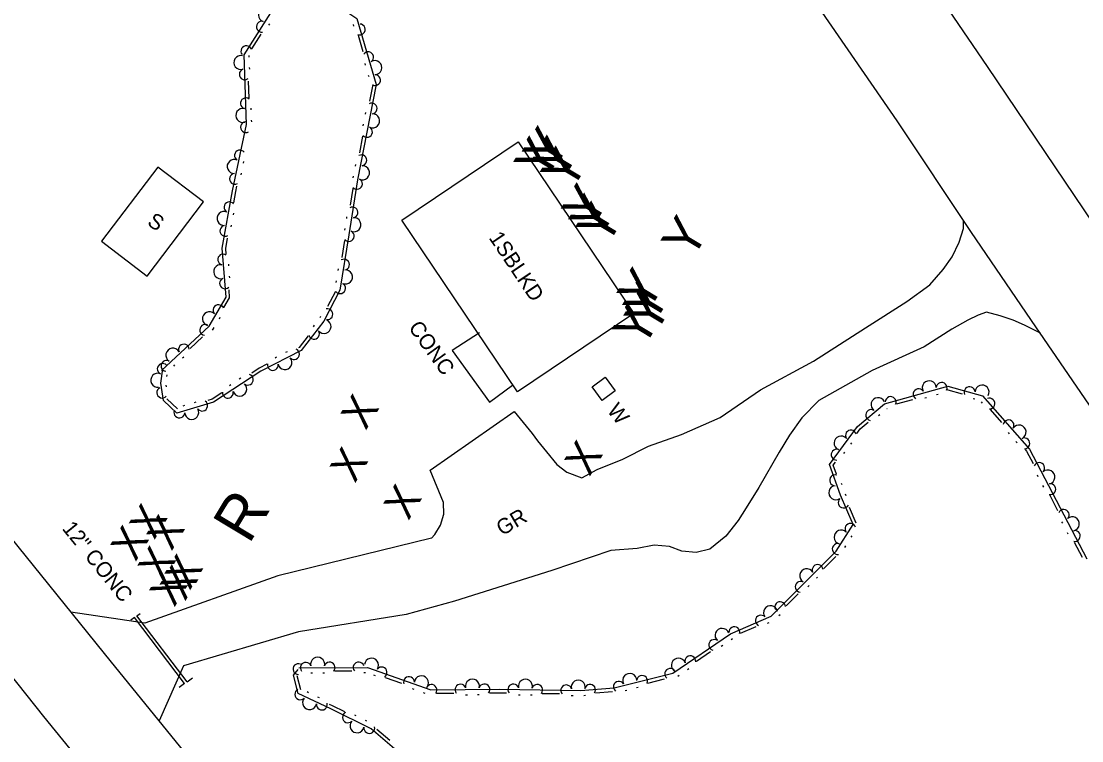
# Model space of a CAD drawing. Extents: x 2030130 to 2036320, y 723205 to 762423.
# Drawn here: x 2033931.4 to 2034186.4, y 759960.9 to 760133.9 of the extents above; entities that cross this region are included whole.
import ezdxf

# ---------------------------------------------------------------- set-up
doc = ezdxf.new("R2010")
doc.units = 0
for name, color, linetype in [('Draft_Station Cardinal Points', 7, 'Continuous'), ('Draft_Station Labels Major', 7, 'Continuous'), ('Draft_Station Tics Major', 7, 'Continuous'), ('Draft_Station Tics Minor', 7, 'Continuous'), ('Exist Terrain Model Ground Surface', 7, 'Continuous'), ('Old_Level_23', 7, 'Continuous'), ('Old_Level_26', 7, 'Continuous'), ('Old_Level_28', 7, 'Continuous')]:
    doc.layers.add(name, color=color, linetype=linetype)

msp = doc.modelspace()

# ---------------------------------------------------------------- linework, layer by layer
at = {"layer": 'Draft_Station Labels Major'}
for points in [[(2033718.38, 760730.67), (2033746.51, 760689.6), (2033774.62, 760648.49), (2033802.7, 760607.26), (2033830.67, 760566.06), (2033858.89, 760525.01), (2033886.8, 760483.79), (2033914.88, 760442.66), (2033945.45, 760397.69), (2033973.64, 760356.6), (2034001.68, 760315.42), (2034029.6, 760274.28), (2034057.68, 760233.24), (2034085.75, 760192.04), (2034113.77, 760150.87), (2034141.95, 760109.94), (2034159.83, 760083.11), (2034175.33, 760060.45), (2034197.95, 760027.35), (2034226.1, 759986.31), (2034253.95, 759945.01), (2034282.77, 759903.21), (2034311.52, 759860.74)], [(2034332.4, 759875.51), (2034304.28, 759916.6), (2034275.65, 759958.8), (2034247.14, 760000.6), (2034219.84, 760040.78), (2034191.61, 760081.68), (2034163.74, 760123.03), (2034135.88, 760163.98), (2034107.11, 760206.11), (2034080.34, 760245.23), (2034051.49, 760287.62), (2034022.91, 760329.48), (2033995.09, 760369.99), (2033966.89, 760411.11), (2033935.74, 760457.29), (2033907.97, 760498.26), (2033880.46, 760539.38), (2033851.33, 760582.23)], [(2034030.05, 760009.58), (2034030.88, 760010.51), (2034032.24, 760012.76), (2034033.03, 760015.36), (2034033.01, 760018.15), (2034029.8, 760025.93), (2034049.99, 760040.05), (2034054.29, 760034.81), (2034055.58, 760033.05), (2034057.7, 760030.34), (2034060.25, 760027.35), (2034062.66, 760025.49), (2034066.26, 760024.13), (2034069.95, 760026.16), (2034076.05, 760028.57), (2034082.29, 760031.75), (2034090.19, 760034.56), (2034099.49, 760038.61), (2034109.22, 760045.29), (2034121.91, 760052.16), (2034134.4, 760060.18), (2034144.39, 760066.5), (2034149.91, 760070.54), (2034153.14, 760074.19), (2034155.24, 760077.28), (2034156.93, 760080.74), (2034157.97, 760084.04), (2034157.98, 760085.88)], [(2033870.01, 760081.82), (2033911.82, 760030.81), (2033953.09, 759979.8), (2033994.45, 759928.93), (2034036.28, 759878.71)], [(2033854.41, 760068.47), (2033895.91, 760018.08), (2033936.8, 759966.77), (2033978.27, 759915.85)], [(2034176.39, 760058.91), (2034176.02, 760059.11), (2034172.66, 760060.81), (2034169.92, 760062.02), (2034166.79, 760063.03), (2034163.49, 760063.96), (2034161.5, 760063.2), (2034159.07, 760062.04), (2034155.21, 760059.9), (2034148.51, 760055.6), (2034136.01, 760049.94), (2034123.25, 760042.73), (2034119.1, 760038.56), (2034116.12, 760034.4), (2034113.68, 760030.26), (2034108.76, 760021.76), (2034105.78, 760016.92), (2034103.81, 760013.83), (2034100.88, 760010.08), (2034096.97, 760006.99), (2034093.71, 760006.13), (2034090.29, 760006.5), (2034087.27, 760007.63), (2034083.64, 760007.95), (2034079.57, 760007.11), (2034073.22, 760006.68), (2034059.04, 760001.81), (2034035.62, 759994.43), (2034023.96, 759991.23)], [(2034030.05, 760009.58), (2033993.17, 760000.52), (2033961.18, 759989.15), (2033943.35, 759991.84)], [(2034023.96, 759991.23), (2033998.09, 759987.07), (2033970.46, 759978.93), (2033964.58, 759965.66)]]:
    msp.add_lwpolyline(points, dxfattribs=at)
at = {"layer": 'Draft_Station Tics Major'}
for points in [[(2033965.17, 760049.92), (2033976.64, 760060.6), (2033980.72, 760067.59), (2033979.8, 760079.3), (2033982.22, 760093.09), (2033985.65, 760109.07), (2033985.02, 760125.83), (2033993.57, 760139.26), (2034003.02, 760140.7), (2034012.1, 760134.52), (2034016.82, 760118.72), (2034012.32, 760095.77), (2034010.24, 760082.56), (2034008.06, 760069.27), (2034004.22, 760061.81), (2033998.79, 760054.77), (2033989.08, 760049.77), (2033977.71, 760042.31), (2033968.89, 760039.65), (2033965.66, 760042.72), (2033965.01, 760046.89), (2033965.47, 760050.32)], [(2033991.01, 760132.95), (2033991.24, 760133.3)], [(2034011.22, 760133.14), (2034011.34, 760132.75)], [(2033986.92, 760127.29), (2033989.13, 760130.75)], [(2034012.44, 760130.51), (2034013.62, 760126.58)], [(2033986.27, 760125.27), (2033986.25, 760125.68)], [(2033986.38, 760122.4), (2033986.36, 760122.81)], [(2034014.05, 760123.71), (2034014.17, 760123.32)], [(2033986.23, 760115.42), (2033986.08, 760119.51)], [(2034014.87, 760120.96), (2034014.99, 760120.57)], [(2034015.99, 760118.72), (2034015.2, 760114.69)], [(2033986.75, 760112.56), (2033986.73, 760112.97)], [(2034014.24, 760111.96), (2034014.16, 760111.55)], [(2033986.86, 760109.69), (2033986.84, 760110.1)], [(2034013.69, 760109.14), (2034013.61, 760108.73)], [(2034013.54, 760106.24), (2034012.75, 760102.22)], [(2033984.91, 760099.75), (2033985, 760100.16)], [(2034011.8, 760099.48), (2034011.72, 760099.08)], [(2033984.31, 760096.95), (2033984.39, 760097.35)], [(2034011.25, 760096.66), (2034011.17, 760096.26)], [(2033982.55, 760090.23), (2033983.03, 760092.94), (2033983.3, 760094.22)], [(2034011.17, 760093.72), (2034010.53, 760089.67)], [(2033982.46, 760087.33), (2033982.53, 760087.73)], [(2034009.68, 760086.9), (2034009.62, 760086.49)], [(2033981.96, 760084.5), (2033982.03, 760084.9)], [(2034009.24, 760084.06), (2034009.17, 760083.66)], [(2033980.73, 760077.89), (2033980.62, 760079.26), (2033981.06, 760081.74)], [(2034009.18, 760081.17), (2034008.52, 760077.12)], [(2033981.36, 760075.06), (2033981.33, 760075.47)], [(2034007.65, 760074.36), (2034007.58, 760073.95)], [(2033981.59, 760072.2), (2033981.56, 760072.61)], [(2034007.18, 760071.52), (2034007.11, 760071.12)], [(2033980.2, 760065.07), (2033981.56, 760067.4), (2033981.41, 760069.31)], [(2034006.97, 760068.95), (2034005.09, 760065.3)], [(2033979.1, 760062.38), (2033979.31, 760062.74)], [(2034003.41, 760062.93), (2034003.22, 760062.57)], [(2033977.41, 760059.64), (2033977.61, 760059.83), (2033977.86, 760060.26)], [(2034001.87, 760060.79), (2034001.62, 760060.46)], [(2033972.03, 760055.19), (2033975.03, 760057.98)], [(2034000.45, 760058.26), (2033998.25, 760055.42), (2033998.13, 760055.35)], [(2033970.21, 760052.93), (2033970.51, 760053.21)], [(2033992.83, 760053.09), (2033992.47, 760052.9)], [(2033995.39, 760054.4), (2033995.02, 760054.22)], [(2033968.11, 760050.97), (2033968.41, 760051.25)], [(2033990.47, 760051.41), (2033988.66, 760050.48), (2033986.86, 760049.3)], [(2033966.47, 760048.5), (2033966.52, 760048.91)], [(2033984.23, 760048.06), (2033983.89, 760047.84)], [(2033966.39, 760046.01), (2033966.33, 760046.42)], [(2033981.83, 760046.49), (2033981.49, 760046.26)], [(2033998.21, 759978.45), (2034014.71, 759978.54), (2034029.92, 759973.13), (2034046.46, 759973.28), (2034065.88, 759972.97), (2034074, 759973.62), (2034088.09, 759977.12), (2034101.94, 759986.6), (2034111.75, 759990.86), (2034127.41, 760006.45), (2034131.46, 760012.9), (2034128.4, 760019.93), (2034125.74, 760027.32), (2034132.54, 760036.47), (2034138.98, 760041.92), (2034154.19, 760046.15), (2034162.58, 760043.86), (2034173.85, 760031), (2034187.64, 760004.61)], [(2034154.14, 760045.28), (2034154.19, 760045.3), (2034157.66, 760044.35)], [(2033969, 760040.68), (2033966.42, 760043.12)], [(2033973.43, 760042.3), (2033973.04, 760042.18)], [(2033979.66, 760044.57), (2033977.36, 760043.06), (2033976.3, 760042.74)], [(2034141.89, 760041.88), (2034145.84, 760042.98)], [(2034148.72, 760043.35), (2034149.11, 760043.46)], [(2034151.49, 760044.12), (2034151.88, 760044.23)], [(2034160.32, 760043.2), (2034160.72, 760043.09)], [(2034162.23, 760042.4), (2034162.5, 760042.09)], [(2033970.68, 760041.47), (2033970.29, 760041.35)], [(2034139.57, 760040.81), (2034139.63, 760040.82)], [(2034164.43, 760040.51), (2034167.13, 760037.42)], [(2034132.32, 760034.79), (2034133.14, 760035.9), (2034135.07, 760037.53)], [(2034137.53, 760039.08), (2034137.84, 760039.34)], [(2034168.71, 760034.99), (2034168.98, 760034.68)], [(2034130.93, 760032.24), (2034131.18, 760032.57)], [(2034170.6, 760032.83), (2034170.88, 760032.52)], [(2034129.22, 760029.94), (2034129.47, 760030.27)], [(2034172.8, 760030.94), (2034173.16, 760030.53), (2034174.72, 760027.56)], [(2034127.46, 760024.96), (2034126.66, 760027.18), (2034127.18, 760027.88)], [(2034175.69, 760024.82), (2034175.88, 760024.46)], [(2034128.82, 760022.4), (2034128.68, 760022.79)], [(2034177.02, 760022.28), (2034177.21, 760021.91)], [(2034129.8, 760019.79), (2034129.64, 760020.17)], [(2034178.71, 760019.92), (2034180.61, 760016.29)], [(2034132.2, 760013.23), (2034130.57, 760016.99)], [(2034181.57, 760013.55), (2034181.77, 760013.19)], [(2034130.98, 760009.82), (2034131.2, 760010.17)], [(2034182.9, 760011.01), (2034183.09, 760010.65)], [(2034129.45, 760007.39), (2034129.67, 760007.73)], [(2034184.6, 760008.66), (2034186.5, 760005.02)], [(2034124.38, 760002.28), (2034127.29, 760005.17)], [(2034122.63, 759999.96), (2034122.92, 760000.25)], [(2034120.6, 759997.94), (2034120.89, 759998.22)], [(2034115.37, 759993.31), (2034118.28, 759996.2)], [(2034113.62, 759990.99), (2034113.92, 759991.28)], [(2034110.91, 759989.16), (2034111.29, 759989.32)], [(2034104.35, 759986.75), (2034108.11, 759988.39)], [(2034099.77, 759983.62), (2034100.11, 759983.85)], [(2034102.14, 759985.24), (2034102.48, 759985.47)], [(2034093.79, 759980.03), (2034097.17, 759982.34)], [(2034025.69, 759955.1), (2034015.57, 759963.76), (2034005.92, 759968.55), (2033998.03, 759972.3), (2033996.91, 759976.7), (2033998.02, 759978.04)], [(2033998.66, 759973.14), (2033997.81, 759976.5)], [(2034001.09, 759977.24), (2034001.5, 759977.24)], [(2034003.96, 759977.25), (2034004.37, 759977.26)], [(2034006.83, 759977.68), (2034010.93, 759977.7)], [(2034013.81, 759977.3), (2034014.22, 759977.31)], [(2034016.14, 759976.72), (2034016.53, 759976.58)], [(2034018.99, 759976.15), (2034022.85, 759974.77)], [(2034089.28, 759976.45), (2034089.62, 759976.68)], [(2034091.65, 759978.07), (2034091.99, 759978.3)], [(2034025.42, 759973.43), (2034025.81, 759973.29)], [(2034079.41, 759973.7), (2034079.81, 759973.8)], [(2034082.1, 759974.79), (2034086.08, 759975.78)], [(2034000.55, 759972.46), (2034000.18, 759972.64)], [(2034003.14, 759971.23), (2034002.77, 759971.41)], [(2034028.12, 759972.47), (2034028.51, 759972.33)], [(2034031.33, 759972.33), (2034035.43, 759972.36)], [(2034038.3, 759971.98), (2034038.71, 759971.98)], [(2034041.17, 759972), (2034041.58, 759972.01)], [(2034044.04, 759972.44), (2034046.46, 759972.46), (2034048.12, 759972.43)], [(2034050.99, 759971.98), (2034051.4, 759971.97)], [(2034053.86, 759971.93), (2034054.27, 759971.93)], [(2034056.73, 759972.3), (2034060.83, 759972.23)], [(2034063.7, 759971.78), (2034064.11, 759971.77)], [(2034066.68, 759971.8), (2034067.09, 759971.83)], [(2034069.51, 759972.44), (2034073.6, 759972.77)], [(2034076.63, 759973.01), (2034077.03, 759973.1)], [(2034009.25, 759967.82), (2034006.28, 759969.29), (2034005.56, 759969.63)], [(2034012.01, 759966.91), (2034011.64, 759967.09)], [(2034014.58, 759965.63), (2034014.21, 759965.81)], [(2034020.09, 759960.97), (2034016.98, 759963.64)]]:
    msp.add_lwpolyline(points, dxfattribs=at)
for centre, radius, start, end in [((2033990.17, 760135.44), 1.69, 43.4477, 251.5202), ((2033989.32, 760132.58), 1.3, 75.9189, 276.7155), ((2034012.87, 760131.92), 1.3, 247.4322, 88.2288), ((2033985.57, 760126.7), 1.3, 18.2525, 219.049), ((2034014.87, 760125.24), 1.3, 305.0987, 145.8953), ((2033984.27, 760123.96), 1.69, 78.1239, 286.1964), ((2034016.48, 760122.73), 1.69, 272.6275, 120.7), ((2033985.19, 760121.12), 1.3, 110.5951, 311.3917), ((2034016.52, 760119.74), 1.3, 247.4322, 88.2288), ((2033985.46, 760114.15), 1.3, 52.9287, 253.7252), ((2034015.69, 760112.93), 1.3, 277.3405, 118.1371), ((2033984.75, 760111.25), 1.69, 78.1239, 286.1964), ((2034015.94, 760109.95), 1.69, 244.8693, 92.9418), ((2033985.51, 760108.43), 1.3, 96.3295, 297.1261), ((2034014.58, 760107.29), 1.3, 219.6741, 60.4706), ((2033984.05, 760101.61), 1.3, 38.6631, 239.4596), ((2034013.24, 760100.45), 1.3, 277.3405, 118.1371), ((2033982.65, 760098.98), 1.69, 63.8584, 271.9308), ((2034013.49, 760097.47), 1.69, 244.8693, 92.9418), ((2033982.85, 760096), 1.3, 96.3295, 297.1261), ((2034012.17, 760094.81), 1.3, 221.824, 62.6206), ((2033980.22, 760086.47), 1.69, 65.9807, 274.0531), ((2033981.53, 760089.16), 1.3, 40.7854, 241.582), ((2034011.09, 760087.92), 1.3, 279.4905, 120.287), ((2034011.45, 760084.96), 1.69, 247.0193, 95.0918), ((2033980.53, 760083.5), 1.3, 98.4519, 299.2484), ((2034010.19, 760082.25), 1.3, 221.4163, 62.2128), ((2033980.01, 760076.6), 1.3, 55.2973, 256.0938), ((2033979.42, 760073.68), 1.69, 80.4925, 288.565), ((2034009.06, 760075.37), 1.3, 279.0827, 119.8793), ((2034009.4, 760072.41), 1.69, 246.6115, 94.684), ((2033980.46, 760070.88), 1.3, 112.9637, 313.7603), ((2034008.13, 760069.71), 1.3, 221.4163, 62.2128), ((2033978.87, 760064.42), 1.3, 20.4481, 221.2447), ((2033976.71, 760062.36), 1.69, 45.6434, 253.7159), ((2034005.07, 760063.47), 1.3, 261.1881, 101.9846), ((2033975.67, 760059.7), 1.3, 61.4206, 262.2171), ((2034004.25, 760060.51), 1.69, 218.3484, 66.4209), ((2034001.85, 760058.74), 1.3, 193.1532, 33.9497), ((2033967.91, 760053.59), 1.69, 28.9494, 237.0219), ((2033970.57, 760054.95), 1.3, 3.7541, 204.5507), ((2033997.04, 760053.87), 1.3, 225.6657, 66.4623), ((2033994.86, 760051.83), 1.69, 193.1945, 41.267), ((2033965.47, 760050.29), 1.3, 43.1676, 243.9641), ((2033966.37, 760051.03), 1.3, 61.4206, 262.2171), ((2033991.94, 760051.25), 1.3, 167.9992, 8.7958), ((2033964.27, 760047.56), 1.69, 68.3628, 276.4353), ((2033985.94, 760047.71), 1.3, 231.7377, 72.5343), ((2034149.75, 760045.77), 1.69, 1.5027, 209.5752), ((2033965.36, 760044.61), 1.3, 117.2286, 318.0251), ((2033981.14, 760044.56), 1.3, 174.0713, 14.8678), ((2033983.99, 760045.45), 1.69, 199.2665, 47.339), ((2034147.2, 760044.21), 1.3, 33.9739, 234.7705), ((2034152.74, 760045.74), 1.3, 336.3074, 177.104), ((2034159.46, 760044.71), 1.3, 3.158, 203.9546), ((2034162.45, 760044.74), 1.69, 330.6868, 178.7593), ((2033974.96, 760041.48), 1.3, 215.2226, 56.0192), ((2034137.45, 760041.7), 1.69, 26.2178, 234.2903), ((2034140.49, 760042.34), 1.3, 336.3074, 177.104), ((2034164.23, 760041.97), 1.3, 271.9883, 112.7849), ((2033969.47, 760039.82), 1.3, 157.5562, 358.3527), ((2033972.45, 760039.86), 1.69, 182.7514, 30.8239), ((2034135.79, 760039.22), 1.3, 58.689, 259.4855), ((2034168.83, 760036.73), 1.3, 329.6548, 170.4513), ((2034130.92, 760034.29), 1.3, 14.1617, 214.9583), ((2034171.34, 760035.11), 1.69, 297.1836, 145.2561), ((2034128.55, 760032.48), 1.69, 39.357, 247.4295), ((2034172.61, 760032.41), 1.3, 271.9883, 112.7849), ((2034127.5, 760029.68), 1.3, 71.8282, 272.6247), ((2034176.21, 760026.48), 1.3, 316.0284, 156.825), ((2034127.11, 760023.53), 1.3, 70.5507, 271.3473), ((2034178.26, 760024.32), 1.69, 283.5572, 131.6297), ((2034127.31, 760020.55), 1.69, 95.746, 303.8185), ((2034178.87, 760021.39), 1.3, 258.3619, 99.1585), ((2034129.16, 760018.17), 1.3, 131.9088, 332.7054), ((2034182.1, 760015.22), 1.3, 316.0284, 156.825), ((2034184.15, 760013.05), 1.69, 283.5572, 131.6297), ((2034130.81, 760011.86), 1.3, 18.6426, 219.4392), ((2034128.59, 760009.87), 1.69, 43.8379, 251.9104), ((2034184.75, 760010.13), 1.3, 258.3619, 99.1585), ((2034127.75, 760007), 1.3, 76.3091, 277.1057), ((2034120.31, 760000.55), 1.69, 30.8359, 238.9084), ((2034122.93, 760001.99), 1.3, 5.6406, 206.4372), ((2034118.86, 759997.94), 1.3, 63.3071, 264.1037), ((2034113.92, 759993.02), 1.3, 5.6406, 206.4372), ((2034111.6, 759991.69), 1.69, 9.4693, 217.5418), ((2034109.29, 759989.79), 1.3, 41.9405, 242.7371), ((2034099.97, 759986.24), 1.69, 20.3208, 228.3932), ((2034102.9, 759987.01), 1.3, 344.2741, 185.0706), ((2034098.06, 759983.94), 1.3, 52.792, 253.5885), ((2034002.72, 759979.3), 1.69, 346.2544, 194.3269), ((2034092.31, 759980.01), 1.3, 355.1255, 195.9221), ((2033998.1, 759978.14), 1.3, 68.9478, 269.7443), ((2033999.85, 759978.46), 1.3, 18.7256, 219.5222), ((2034005.6, 759978.49), 1.3, 321.0591, 161.8557), ((2034012.57, 759978.53), 1.3, 18.7256, 219.5222), ((2034015.67, 759979.07), 1.69, 326.4115, 174.484), ((2034018.1, 759977.33), 1.3, 301.2163, 142.0128), ((2034089.47, 759979.07), 1.69, 20.3208, 228.3932), ((2034024.67, 759975), 1.3, 358.8827, 199.6793), ((2034027.65, 759974.81), 1.69, 326.4115, 174.484), ((2034077.73, 759975.39), 1.69, 359.9317, 208.0042), ((2034080.71, 759975.29), 1.3, 334.7364, 175.533), ((2034087.48, 759976.97), 1.3, 32.4029, 233.1995), ((2034030.09, 759973.13), 1.3, 321.2742, 162.0707), ((2034037.06, 759973.2), 1.3, 18.9406, 219.7372), ((2034039.93, 759974.04), 1.69, 346.4695, 194.5419), ((2034042.8, 759973.25), 1.3, 321.2742, 162.0707), ((2034049.77, 759973.23), 1.3, 17.5251, 218.3217), ((2034052.66, 759974), 1.69, 345.054, 193.1264), ((2034055.52, 759973.14), 1.3, 319.8587, 160.6552), ((2034062.49, 759973.02), 1.3, 17.5251, 218.3217), ((2034065.37, 759973.8), 1.69, 345.054, 193.1264), ((2034068.22, 759973.16), 1.3, 325.3394, 166.136), ((2034075.14, 759973.9), 1.3, 32.4029, 233.1995), ((2033998.54, 759972.06), 1.3, 115.4036, 316.2002), ((2034000.78, 759970.08), 1.69, 140.5989, 348.6714), ((2034003.73, 759969.6), 1.3, 173.0701, 13.8667), ((2034009.99, 759966.53), 1.3, 114.3498, 315.1464), ((2034012.2, 759964.52), 1.69, 139.5451, 347.6176), ((2034015.13, 759963.98), 1.3, 172.0163, 12.8129)]:
    msp.add_arc(centre, radius, start, end, dxfattribs=at)
at = {"layer": 'Draft_Station Tics Minor'}
for p, q in [((2033959.25, 759990.92), (2033960.05, 759991.52)), ((2033958.68, 759990.54), (2033957.8, 759989.86)), ((2033971.31, 759975.04), (2033972.62, 759976.04)), ((2033970.74, 759974.67), (2033969.43, 759973.67))]:
    msp.add_line(p, q, dxfattribs=at)
for points in [[(2033970.74, 759974.67), (2033958.68, 759990.54)], [(2033971.31, 759975.04), (2033959.25, 759990.92)]]:
    msp.add_lwpolyline(points, dxfattribs=at)
at = {"layer": 'Exist Terrain Model Ground Surface'}
for points in [[(2034050.8, 760044.83), (2034022.99, 760086.06), (2034050.89, 760104.88), (2034078.7, 760063.66)], [(2033964.29, 760098.81), (2033950.74, 760081.01), (2033961.74, 760072.64), (2033975.28, 760090.44)], [(2034071.82, 760048.3), (2034074.22, 760045.06), (2034071.1, 760042.75), (2034068.7, 760045.98)]]:
    msp.add_lwpolyline(points, close=True, dxfattribs=at)
msp.add_lwpolyline([(2034041.59, 760058.98), (2034035.05, 760054.77), (2034044.02, 760042.32), (2034049.55, 760046.43)], dxfattribs=at)

# ---------------------------------------------------------------- texts
at = {"layer": 'Draft_Station Cardinal Points'}
msp.add_text('R', height=10.66, rotation=58.9267, dxfattribs=at).set_placement((2033986.22, 760007.96))
at = {"layer": 'Draft_Station Tics Major'}
for s, height, p in [('Y', 9.02, (2034059.33, 760097.66)), ('Y', 9.02, (2034057.3, 760095.17)), ('Y', 9.02, (2034061.54, 760095.38)), ('Y', 9.02, (2034063.66, 760092.75)), ('Y', 9.02, (2034068.71, 760083.93)), ('Y', 9.02, (2034070.5, 760081.42)), ('Y', 9.02, (2034072.19, 760079.52)), ('Y', 9.02, (2034092.7, 760076.27)), ('Y', 9.02, (2034082.09, 760063.71)), ('Y', 9.02, (2034083.47, 760060.8)), ('Y', 9.02, (2034083.75, 760058.24)), ('Y', 9.02, (2034080.93, 760054.91)), ('X', 7.38, (2034014.25, 760035.35)), ('X', 7.38, (2034068.06, 760024.25)), ('X', 7.38, (2034011.65, 760022.66)), ('X', 7.38, (2034024.53, 760013.7)), ('X', 7.38, (2033963.41, 760009.03)), ('X', 7.38, (2033967.57, 760006.36)), ('X', 7.38, (2033958.92, 760003.79)), ('X', 7.38, (2033965.46, 759998.85)), ('X', 7.38, (2033971.94, 759996.88)), ('X', 7.38, (2033968.24, 759992.86)), ('X', 7.38, (2033970.8, 759994.28))]:
    msp.add_text(s, height=height, rotation=58.9267, dxfattribs=at).set_placement(p)
at = {"layer": 'Old_Level_23'}
msp.add_text('GR', height=3.691, rotation=30.5576, dxfattribs=at).set_placement((2034047.05, 760010.06))
at = {"layer": 'Old_Level_26'}
msp.add_text('12" CONC', height=3.691, rotation=308.9588, dxfattribs=at).set_placement((2033941.12, 760011.88))
at = {"layer": 'Old_Level_28'}
for s, height, rotation, p in [('S', 3.69, 327.0996, (2033961.5, 760085.04)), ('1SBLKD', 3.691, 304.0038, (2034043.75, 760081.83)), ('CONC', 3.691, 305.7699, (2034024.4, 760060.22)), ('W', 3.69, 308.0887, (2034072.14, 760040.25))]:
    msp.add_text(s, height=height, rotation=rotation, dxfattribs=at).set_placement(p)

doc.saveas('drawing.dxf')
